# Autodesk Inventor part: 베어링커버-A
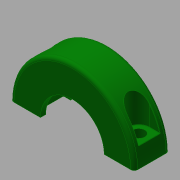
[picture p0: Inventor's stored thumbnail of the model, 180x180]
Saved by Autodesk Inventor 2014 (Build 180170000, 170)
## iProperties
Created: 2018-01
Part Number: 베어링커버-A
Material: 일반
Document SubType Name: Modeling
Designer: mduedu
Density: 1 g/cm^3
Appearance: 진녹색
Author: mduedu
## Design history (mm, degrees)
sketch "스케치1"
  geometry: L1 (-17.5, 0)-(17.5, 0); A1 r 17.5 centre (0, 0) between (-17.5, 0) and (17.5, 0); 2 further points
  constraints: 2 coincident, 2 end point, 2 point on circle, 1 centre point, 1 horizontal, 1 midpoint
  dimensions: "d0" = 35 diameter of A1
extrude "돌출1" new body sketch "스케치1" stored distance "d1" = 10; taper "d2" = 0 deg
sketch "스케치2"
  geometry: C1 r 11 at (0, 0); C2 r 9 at (0, 0); 1 further point
  constraints: 2 centre point, 2 coincident
  dimensions: "d3" = 22 diameter of C1; "d4" = 18 diameter of C2
extrude "돌출2" cut sketch "스케치2" stored distance "d5" = 7; taper "d6" = 0 deg
extrude "돌출3" cut sketch "스케치2" stored distance "d7" = 7; taper "d8" = 0 deg
fillet "모깎기1" dims "d9" = 0.3
fillet "모깎기2" dims "d10" = 1
node "작업 평면1"
sketch "스케치3"
  geometry: L1 (-15.5, -3.5)-(33.5, -3.5) reference; L2 (-4.771, -6.5)-(-7.771, -6.5); L3 (-7.771, -6.5)-(-7.771, -0.5); L4 (-7.771, -0.5)-(-4.771, -0.5); L5 (-0.46, -7)-(1.517, -7) reference; L6 (1.517, -7)-(1.517, -8.5) reference; L7 (1.517, -8.5)-(-6.724, -8.5) reference; L8 (-7.771, -7.5)-(-7.771, 0.5) reference; L9 (-6.724, 1.5)-(1.517, 1.5) reference; L10 (1.517, 1.5)-(1.517, 0) reference; L11 (1.517, 0)-(-0.46, 0) reference; L12 (-0.798, -0.3)-(-0.798, -6.7) reference; L13 (18.798, -6.7)-(18.798, -0.3) reference; L14 (18.46, 0)-(16.483, 0) reference; L15 (16.483, 0)-(16.483, 1.5) reference; L16 (16.483, 1.5)-(24.724, 1.5) reference; L17 (25.771, 0.5)-(25.771, -7.5) reference; L18 (24.724, -8.5)-(16.483, -8.5) reference; L19 (16.483, -8.5)-(16.483, -7) reference; L20 (16.483, -7)-(18.46, -7) reference; A1 r 3 centre (-4.771, -3.5) between (-4.771, -6.5) and (-4.771, -0.5); 1 further point
  constraints: 6 end point, 2 point on circle, 2 tangent, 1 centre point, 1 collinear, 1 horizontal, 1 parallel, 1 perpendicular, 1 point on line, 8 other
  dimensions: "d12" = 6 distance between parallel lines of L4 L2; "d14" = 6 dimension on A1 L3
extrude "돌출4" cut sketch "스케치3" stored distance "d15" = 0; taper "d16" = 0 deg
sketch "스케치4"
  geometry: 7 further points
  constraints: 4 vertical alignment, 2 horizontal alignment
sketch "스케치5"
  geometry: 2 further points
  constraints: 2 other
hole "구멍1" sketch "스케치5" at (-22.771, 3.5), (4.771, 3.5) diameter "d17" = 3.4; stored, may be unused: countersink angle "d21" = 90 deg, drill point angle "d23" = 0 deg; dims "d18" = 6, "d19" = 4, "d20" = 2, "d22" = 8
fillet "모깎기3" dims "d24" = 0.1
node "솔리드1"
mirror "대칭1"
node "절단 모서리 투영1"
other parameters: "d11" = -5
